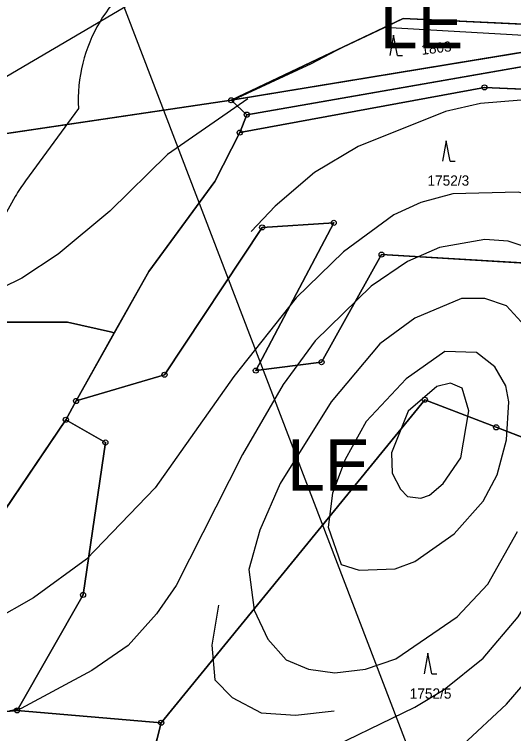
# Model space of a CAD drawing. Extents: x -706130 to -698555, y -971544 to -967260.
# Drawn here: x -703788.9 to -703691, y -970758.1 to -970617.2 of the extents above; entities that cross this region are included whole.
import ezdxf

# ---------------------------------------------------------------- set-up
doc = ezdxf.new("R2010")
doc.units = 0
for name, color, linetype in [('Archeologická naleziště S', 7, 'Continuous'), ('BPEJ hranice S', 7, 'Continuous'), ('BPEJ I-II trida ochrany S', 7, 'Continuous'), ('KN_Hranice_parcel', 7, 'Continuous'), ('KN_Parcelni cisla', 7, 'Continuous'), ('KN_Polygon parcely', 7, 'Continuous'), ('KN_POZEMKY_10_LESNI POZEMEK', 7, 'Continuous'), ('KN_POZEMKY_14_OSTATNI PLOCHA', 7, 'Continuous'), ('KN_POZEMKY_2_ORNA PUDA', 7, 'Continuous'), ('KN_VYUZITI_17_ostatni plocha_ostatni komunikace', 7, 'Continuous'), ('KN_Značky bodu BP', 7, 'Continuous'), ('KN_Značky kultur', 7, 'Continuous'), ('OP lesa 30 m', 7, 'Continuous'), ('Plochy lesní všeobecné S', 7, 'Continuous'), ('Plochy verejnych prostranstvi - komunikace ostatni S', 7, 'Continuous'), ('Plochy zemědělské všeobecné CELEK S', 7, 'Continuous'), ('Regulační bloky v krajině S', 7, 'Continuous'), ('Regulační bloky zastavěné S', 7, 'Continuous'), ('Regulační kódy v krajině S', 7, 'Continuous'), ('VÝŠKOPIS_vrstevnice doplňková', 7, 'Continuous'), ('VÝŠKOPIS_vrstevnice hlavní', 7, 'Continuous'), ('VÝŠKOPIS_vrstevnice zesílená', 7, 'Continuous')]:
    doc.layers.add(name, color=color, linetype=linetype)

msp = doc.modelspace()

# ---------------------------------------------------------------- linework, layer by layer
at = {"layer": 'Archeologická naleziště S'}
msp.add_lwpolyline([(-703408.7, -970993.88), (-703586.12, -970875.94), (-703659.44, -970897.19), (-703878.38, -970326.38), (-703591.19, -970210.38), (-703362.81, -970550.62), (-703335.44, -970886.44), (-703375.42, -970994.48)], dxfattribs=at)
at = {"layer": 'BPEJ hranice S'}
for points in [[(-703611.44, -970647.66), (-703616.01, -970640.13), (-703617.35, -970637.9), (-703628.15, -970631.35), (-703640.72, -970627.1), (-703661.7, -970626.61), (-703663.2, -970626.57), (-703664, -970624.6), (-703664.79, -970622.68), (-703674.27, -970622.13), (-703716.34, -970619.71), (-703724.46, -970623.57), (-703730.69, -970626.83), (-703745.91, -970633.92), (-703746.26, -970634.08), (-703743.32, -970636.82), (-703744.69, -970640.33), (-703749.57, -970649.91), (-703762.54, -970667.56), (-703769.3, -970679.59), (-703770.02, -970679.4), (-703778.45, -970677.49), (-703792, -970677.49)], [(-703796.23, -970722.36), (-703778.8, -970696.59), (-703776.78, -970692.92), (-703769.3, -970679.59), (-703770.02, -970679.4), (-703778.45, -970677.49), (-703792, -970677.49)]]:
    msp.add_lwpolyline(points, dxfattribs=at)
at = {"layer": 'BPEJ I-II trida ochrany S'}
for p, q in [((-703716.34, -970619.71), (-703712.67, -970617.96)), ((-703712.67, -970617.96), (-703663.27, -970620.32)), ((-703746.36, -970633.99), (-703724.46, -970623.57)), ((-703743.32, -970636.82), (-703746.36, -970633.99)), ((-703792, -970677.49), (-703778.45, -970677.49)), ((-703778.45, -970677.49), (-703770.02, -970679.4))]:
    msp.add_line(p, q, dxfattribs=at)
for points in [[(-703724.46, -970623.57), (-703724.46, -970623.57), (-703716.34, -970619.71), (-703716.34, -970619.71)], [(-703770.02, -970679.4), (-703769.3, -970679.59), (-703762.54, -970667.56), (-703749.57, -970649.91), (-703744.69, -970640.33), (-703743.32, -970636.82)]]:
    msp.add_lwpolyline(points, dxfattribs=at)
at = {"layer": 'KN_Hranice_parcel'}
for p, q in [((-703746.36, -970633.99), (-703663.27, -970620.32)), ((-703696.75, -970631.48), (-703744.69, -970640.33)), ((-703665.55, -970632.87), (-703696.75, -970631.48)), ((-703746.36, -970633.99), (-703845.42, -970648.65)), ((-703743.32, -970636.82), (-703746.36, -970633.99)), ((-703743.32, -970636.82), (-703744.69, -970640.33)), ((-703776.78, -970692.92), (-703759.45, -970687.77)), ((-703778.8, -970696.59), (-703776.78, -970692.92)), ((-703771.03, -970701.05), (-703778.8, -970696.59)), ((-703661.78, -970710.7), (-703694.43, -970698.08)), ((-703788.35, -970753.55), (-703835.64, -970758.02)), ((-703760.08, -970755.96), (-703788.35, -970753.55)), ((-703775.02, -970814.32), (-703760.08, -970755.96))]:
    msp.add_line(p, q, dxfattribs=at)
for points in [[(-703663.27, -970620.32), (-703712.67, -970617.96), (-703746.36, -970633.99)], [(-703660.69, -970624.97), (-703669.68, -970623.96), (-703743.32, -970636.82)], [(-703759.45, -970687.77), (-703740.3, -970658.91), (-703726.28, -970658.01), (-703741.54, -970686.96), (-703728.65, -970685.31), (-703716.89, -970664.24), (-703686.1, -970666.05), (-703665.55, -970632.87)], [(-703744.69, -970640.33), (-703749.57, -970649.91), (-703762.54, -970667.56), (-703776.78, -970692.92)], [(-703694.43, -970698.08), (-703708.42, -970692.67), (-703760.08, -970755.96)], [(-703835.64, -970758.02), (-703816.66, -970738.43), (-703796.23, -970722.36), (-703778.8, -970696.59)], [(-703788.35, -970753.55), (-703775.41, -970730.92), (-703771.03, -970701.05)]]:
    msp.add_lwpolyline(points, dxfattribs=at)
at = {"layer": 'KN_Polygon parcely'}
msp.add_lwpolyline([(-703939.69, -970610.55), (-703996, -970622.02), (-703989.78, -970655.74), (-703975.44, -970677.14), (-703944.34, -970667.67), (-703937.82, -970665.9), (-703864.08, -970651.3), (-703845.42, -970648.65), (-703746.36, -970633.99), (-703712.67, -970617.96), (-703663.27, -970620.32), (-703637.5, -970621.77), (-703629.23, -970623.8), (-703613.54, -970631.59), (-703573.25, -970635.06), (-703560.34, -970638.34), (-703550.3, -970642.25), (-703478.57, -970668.92), (-703476.26, -970659.93), (-703472.33, -970642.48), (-703487.91, -970603.31)], dxfattribs=at)
for points in [[(-703746.36, -970633.99), (-703663.27, -970620.32), (-703712.67, -970617.96)], [(-703615.1, -970635.19), (-703579.7, -970637.28), (-703562.88, -970640.25), (-703463.09, -970679), (-703454.84, -970679.15), (-703407.35, -970679.31), (-703407.75, -970675.61), (-703461.8, -970675.15), (-703478.57, -970668.92), (-703550.3, -970642.25), (-703560.34, -970638.34), (-703573.25, -970635.06), (-703613.54, -970631.59), (-703629.23, -970623.8), (-703637.5, -970621.77), (-703663.27, -970620.32), (-703746.36, -970633.99), (-703743.32, -970636.82), (-703669.68, -970623.96), (-703660.69, -970624.97), (-703639.83, -970624.72), (-703629.81, -970627.16)], [(-703669.68, -970623.96), (-703743.32, -970636.82), (-703744.69, -970640.33), (-703696.75, -970631.48), (-703665.55, -970632.87), (-703660.69, -970624.97)], [(-703760.08, -970755.96), (-703708.42, -970692.67), (-703694.43, -970698.08), (-703661.78, -970710.7), (-703651.67, -970713.29), (-703621.65, -970670.96), (-703615.1, -970635.19), (-703629.81, -970627.16), (-703639.83, -970624.72), (-703660.69, -970624.97), (-703665.55, -970632.87), (-703686.1, -970666.05), (-703716.89, -970664.24), (-703728.65, -970685.31), (-703741.54, -970686.96), (-703726.28, -970658.01), (-703740.3, -970658.91), (-703759.45, -970687.77), (-703776.78, -970692.92), (-703778.8, -970696.59), (-703771.03, -970701.05), (-703775.41, -970730.92), (-703788.35, -970753.55)], [(-703716.89, -970664.24), (-703686.1, -970666.05), (-703665.55, -970632.87), (-703696.75, -970631.48), (-703744.69, -970640.33), (-703749.57, -970649.91), (-703762.54, -970667.56), (-703776.78, -970692.92), (-703759.45, -970687.77), (-703740.3, -970658.91), (-703726.28, -970658.01), (-703741.54, -970686.96), (-703728.65, -970685.31)], [(-703778.8, -970696.59), (-703776.78, -970692.92), (-703762.54, -970667.56), (-703749.57, -970649.91), (-703744.69, -970640.33), (-703743.32, -970636.82), (-703746.36, -970633.99), (-703845.42, -970648.65), (-703864.08, -970651.3), (-703937.82, -970665.9), (-703944.34, -970667.67), (-703975.44, -970677.14), (-703961.3, -970781.02), (-703954.28, -970779.83), (-703945.45, -970778.27), (-703944.45, -970781.48), (-703927.53, -970774.91), (-703881.57, -970766.76), (-703835.64, -970758.02), (-703816.66, -970738.43), (-703796.23, -970722.36)], [(-703708.42, -970692.67), (-703760.08, -970755.96), (-703775.02, -970814.32), (-703732.08, -970781.35), (-703683.41, -970785.58), (-703676.23, -970759.35), (-703661.78, -970710.7), (-703694.43, -970698.08)], [(-703775.41, -970730.92), (-703771.03, -970701.05), (-703778.8, -970696.59), (-703796.23, -970722.36), (-703816.66, -970738.43), (-703835.64, -970758.02), (-703788.35, -970753.55)], [(-703775.02, -970814.32), (-703760.08, -970755.96), (-703788.35, -970753.55), (-703835.64, -970758.02), (-703881.57, -970766.76), (-703856.96, -970809.13), (-703851.88, -970814.56), (-703846.84, -970815.09), (-703839.77, -970813.83), (-703775.76, -970818.75), (-703772.64, -970816.86)]]:
    msp.add_lwpolyline(points, close=True, dxfattribs=at)
at = {"layer": 'KN_POZEMKY_10_LESNI POZEMEK'}
for p, q in [((-703746.36, -970633.99), (-703712.67, -970617.96)), ((-703712.67, -970617.96), (-703663.27, -970620.32)), ((-703663.27, -970620.32), (-703746.36, -970633.99)), ((-703743.32, -970636.82), (-703669.68, -970623.96)), ((-703696.75, -970631.48), (-703744.69, -970640.33)), ((-703744.69, -970640.33), (-703696.75, -970631.48)), ((-703665.55, -970632.87), (-703696.75, -970631.48)), ((-703696.75, -970631.48), (-703665.55, -970632.87)), ((-703744.69, -970640.33), (-703743.32, -970636.82)), ((-703749.57, -970649.91), (-703744.69, -970640.33)), ((-703762.54, -970667.56), (-703749.57, -970649.91)), ((-703726.28, -970658.01), (-703741.54, -970686.96)), ((-703741.54, -970686.96), (-703726.28, -970658.01)), ((-703740.3, -970658.91), (-703726.28, -970658.01)), ((-703726.28, -970658.01), (-703740.3, -970658.91)), ((-703759.45, -970687.77), (-703740.3, -970658.91)), ((-703740.3, -970658.91), (-703759.45, -970687.77)), ((-703728.65, -970685.31), (-703716.89, -970664.24)), ((-703716.89, -970664.24), (-703728.65, -970685.31)), ((-703716.89, -970664.24), (-703686.1, -970666.05)), ((-703686.1, -970666.05), (-703716.89, -970664.24)), ((-703776.78, -970692.92), (-703762.54, -970667.56)), ((-703741.54, -970686.96), (-703728.65, -970685.31)), ((-703728.65, -970685.31), (-703741.54, -970686.96)), ((-703776.78, -970692.92), (-703759.45, -970687.77)), ((-703759.45, -970687.77), (-703776.78, -970692.92)), ((-703778.8, -970696.59), (-703776.78, -970692.92)), ((-703708.42, -970692.67), (-703760.08, -970755.96)), ((-703760.08, -970755.96), (-703708.42, -970692.67)), ((-703694.43, -970698.08), (-703708.42, -970692.67)), ((-703708.42, -970692.67), (-703694.43, -970698.08)), ((-703796.23, -970722.36), (-703778.8, -970696.59)), ((-703771.03, -970701.05), (-703778.8, -970696.59)), ((-703778.8, -970696.59), (-703771.03, -970701.05)), ((-703661.78, -970710.7), (-703694.43, -970698.08)), ((-703694.43, -970698.08), (-703661.78, -970710.7)), ((-703775.41, -970730.92), (-703771.03, -970701.05)), ((-703771.03, -970701.05), (-703775.41, -970730.92)), ((-703788.35, -970753.55), (-703775.41, -970730.92)), ((-703775.41, -970730.92), (-703788.35, -970753.55)), ((-703835.64, -970758.02), (-703788.35, -970753.55)), ((-703788.35, -970753.55), (-703835.64, -970758.02)), ((-703788.35, -970753.55), (-703760.08, -970755.96)), ((-703760.08, -970755.96), (-703788.35, -970753.55)), ((-703760.08, -970755.96), (-703775.02, -970814.32)), ((-703775.02, -970814.32), (-703760.08, -970755.96))]:
    msp.add_line(p, q, dxfattribs=at)
at = {"layer": 'KN_POZEMKY_14_OSTATNI PLOCHA'}
for p, q in [((-703746.36, -970633.99), (-703663.27, -970620.32)), ((-703669.68, -970623.96), (-703743.32, -970636.82)), ((-703743.32, -970636.82), (-703746.36, -970633.99))]:
    msp.add_line(p, q, dxfattribs=at)
at = {"layer": 'KN_POZEMKY_2_ORNA PUDA'}
for p, q in [((-703712.67, -970617.96), (-703746.36, -970633.99)), ((-703663.27, -970620.32), (-703712.67, -970617.96)), ((-703845.42, -970648.65), (-703746.36, -970633.99)), ((-703746.36, -970633.99), (-703845.42, -970648.65)), ((-703746.36, -970633.99), (-703743.32, -970636.82)), ((-703743.32, -970636.82), (-703744.69, -970640.33)), ((-703744.69, -970640.33), (-703749.57, -970649.91)), ((-703749.57, -970649.91), (-703762.54, -970667.56)), ((-703762.54, -970667.56), (-703776.78, -970692.92)), ((-703776.78, -970692.92), (-703778.8, -970696.59)), ((-703778.8, -970696.59), (-703796.23, -970722.36))]:
    msp.add_line(p, q, dxfattribs=at)
at = {"layer": 'KN_VYUZITI_17_ostatni plocha_ostatni komunikace'}
for p, q in [((-703746.36, -970633.99), (-703663.27, -970620.32)), ((-703669.68, -970623.96), (-703743.32, -970636.82)), ((-703743.32, -970636.82), (-703746.36, -970633.99))]:
    msp.add_line(p, q, dxfattribs=at)
at = {"layer": 'KN_Značky bodu BP'}
for centre, radius in [((-703696.75, -970631.48), 0.5), ((-703696.75, -970631.48), 0.0303), ((-703746.36, -970633.99), 0.5), ((-703746.36, -970633.99), 0.0303), ((-703743.32, -970636.82), 0.5), ((-703743.32, -970636.82), 0.0303), ((-703744.69, -970640.33), 0.5), ((-703744.69, -970640.33), 0.0303), ((-703726.28, -970658.01), 0.5), ((-703726.28, -970658.01), 0.0303), ((-703740.3, -970658.91), 0.5), ((-703740.3, -970658.91), 0.0303), ((-703716.89, -970664.24), 0.5), ((-703716.89, -970664.24), 0.0303), ((-703728.65, -970685.31), 0.5), ((-703741.54, -970686.96), 0.5), ((-703728.65, -970685.31), 0.0303), ((-703759.45, -970687.77), 0.5), ((-703759.45, -970687.77), 0.0303), ((-703741.54, -970686.96), 0.0303), ((-703708.42, -970692.67), 0.5), ((-703776.78, -970692.92), 0.5), ((-703776.78, -970692.92), 0.0303), ((-703708.42, -970692.67), 0.0303), ((-703778.8, -970696.59), 0.5), ((-703778.8, -970696.59), 0.0303), ((-703694.43, -970698.08), 0.5), ((-703694.43, -970698.08), 0.0303), ((-703771.03, -970701.05), 0.5), ((-703771.03, -970701.05), 0.0303), ((-703775.41, -970730.92), 0.5), ((-703775.41, -970730.92), 0.0303), ((-703788.35, -970753.55), 0.5), ((-703788.35, -970753.55), 0.0303), ((-703760.08, -970755.96), 0.5), ((-703760.08, -970755.96), 0.0303)]:
    msp.add_circle(centre, radius, dxfattribs=at)
at = {"layer": 'KN_Značky kultur'}
for p, q in [((-703714.54, -970621.22), (-703715.29, -970625.22)), ((-703713.79, -970625.22), (-703714.54, -970621.22)), ((-703713.79, -970625.22), (-703712.79, -970625.22)), ((-703704.22, -970641.96), (-703704.97, -970645.96)), ((-703703.47, -970645.96), (-703704.22, -970641.96)), ((-703703.47, -970645.96), (-703702.47, -970645.96)), ((-703707.81, -970742.36), (-703708.56, -970746.36)), ((-703707.06, -970746.36), (-703707.81, -970742.36)), ((-703707.06, -970746.36), (-703706.06, -970746.36))]:
    msp.add_line(p, q, dxfattribs=at)
at = {"layer": 'OP lesa 30 m'}
for p, q in [((-703776.31, -970635.64), (-703786.71, -970649.8)), ((-703788.7, -970652.87), (-703802.94, -970678.23))]:
    msp.add_line(p, q, dxfattribs=at)
for centre, start, end in [((-703746.36, -970633.99), 115.4455, 183.1573), ((-703762.54, -970667.56), 143.6899, 150.6852)]:
    msp.add_arc(centre, 30, start, end, dxfattribs=at)
at = {"layer": 'Plochy lesní všeobecné S'}
for p, q in [((-703712.67, -970617.96), (-703746.36, -970633.99)), ((-703663.27, -970620.32), (-703712.67, -970617.96)), ((-703746.36, -970633.99), (-703663.27, -970620.32)), ((-703669.68, -970623.96), (-703743.32, -970636.82)), ((-703743.32, -970636.82), (-703744.69, -970640.33)), ((-703744.69, -970640.33), (-703749.57, -970649.91)), ((-703749.57, -970649.91), (-703762.54, -970667.56)), ((-703762.54, -970667.56), (-703776.78, -970692.92)), ((-703776.78, -970692.92), (-703778.8, -970696.59)), ((-703778.8, -970696.59), (-703796.23, -970722.36))]:
    msp.add_line(p, q, dxfattribs=at)
at = {"layer": 'Plochy verejnych prostranstvi - komunikace ostatni S'}
for p, q in [((-703743.32, -970636.82), (-703669.68, -970623.96)), ((-703746.36, -970633.99), (-703743.32, -970636.82))]:
    msp.add_line(p, q, dxfattribs=at)
msp.add_lwpolyline([(-703629.23, -970623.8), (-703637.5, -970621.77), (-703663.27, -970620.32), (-703746.36, -970633.99)], dxfattribs=at)
at = {"layer": 'Plochy zemědělské všeobecné CELEK S'}
for p, q in [((-703746.36, -970633.99), (-703712.67, -970617.96)), ((-703712.67, -970617.96), (-703663.27, -970620.32)), ((-703743.32, -970636.82), (-703746.36, -970633.99)), ((-703744.69, -970640.33), (-703743.32, -970636.82)), ((-703749.57, -970649.91), (-703744.69, -970640.33)), ((-703762.54, -970667.56), (-703749.57, -970649.91)), ((-703776.78, -970692.92), (-703762.54, -970667.56)), ((-703778.8, -970696.59), (-703776.78, -970692.92)), ((-703796.23, -970722.36), (-703778.8, -970696.59))]:
    msp.add_line(p, q, dxfattribs=at)
at = {"layer": 'Regulační bloky v krajině S'}
for p, q in [((-703712.67, -970617.96), (-703746.36, -970633.99)), ((-703746.36, -970633.99), (-703712.67, -970617.96)), ((-703663.27, -970620.32), (-703712.67, -970617.96)), ((-703712.67, -970617.96), (-703663.27, -970620.32)), ((-703746.36, -970633.99), (-703663.27, -970620.32)), ((-703669.68, -970623.96), (-703743.32, -970636.82)), ((-703743.32, -970636.82), (-703746.36, -970633.99)), ((-703743.32, -970636.82), (-703744.69, -970640.33)), ((-703744.69, -970640.33), (-703743.32, -970636.82)), ((-703744.69, -970640.33), (-703749.57, -970649.91)), ((-703749.57, -970649.91), (-703744.69, -970640.33)), ((-703749.57, -970649.91), (-703762.54, -970667.56)), ((-703762.54, -970667.56), (-703749.57, -970649.91)), ((-703762.54, -970667.56), (-703776.78, -970692.92)), ((-703776.78, -970692.92), (-703762.54, -970667.56)), ((-703776.78, -970692.92), (-703778.8, -970696.59)), ((-703778.8, -970696.59), (-703776.78, -970692.92)), ((-703778.8, -970696.59), (-703796.23, -970722.36)), ((-703796.23, -970722.36), (-703778.8, -970696.59))]:
    msp.add_line(p, q, dxfattribs=at)
at = {"layer": 'Regulační bloky zastavěné S'}
for p, q in [((-703743.32, -970636.82), (-703669.68, -970623.96)), ((-703746.36, -970633.99), (-703743.32, -970636.82))]:
    msp.add_line(p, q, dxfattribs=at)
msp.add_lwpolyline([(-703629.23, -970623.8), (-703637.5, -970621.77), (-703663.27, -970620.32), (-703746.36, -970633.99)], dxfattribs=at)
at = {"layer": 'VÝŠKOPIS_vrstevnice doplňková'}
for points in [[(-703704.8, -970709.09), (-703701.38, -970704.08), (-703699.81, -970694.82), (-703701.09, -970690.4), (-703703.38, -970689.4), (-703706.04, -970690.08), (-703711.66, -970694.89), (-703714.93, -970703.1), (-703714.79, -970707.09), (-703713.22, -970710.23), (-703711.79, -970711.66), (-703709.23, -970711.94), (-703707.51, -970711.37), (-703704.8, -970709.09)], [(-703748.89, -970732.92), (-703750.17, -970740.76), (-703749.59, -970747.58), (-703746.18, -970751.04), (-703740.47, -970754.03), (-703733.77, -970754.46), (-703726.2, -970753.6)]]:
    msp.add_lwpolyline(points, dxfattribs=at)
at = {"layer": 'VÝŠKOPIS_vrstevnice hlavní'}
for points in [[(-703762.3, -970612.79), (-703794.54, -970631.76), (-703804.82, -970637.04), (-703810.52, -970638.75), (-703818.51, -970639.18), (-703828.5, -970637.61), (-703865.02, -970626.77), (-703873.01, -970626.2), (-703881.57, -970627.34), (-703890.13, -970630.05)], [(-703743.12, -970633.7), (-703758.88, -970644.6), (-703770.15, -970655.73), (-703780.28, -970664.15), (-703787.41, -970668.86), (-703795.33, -970672.68), (-703853.32, -970692.54), (-703864.45, -970698.11), (-703872.73, -970705.1), (-703884, -970718.79)], [(-703649.02, -970664.01), (-703653.73, -970654.02), (-703658.15, -970648.03), (-703665.57, -970640.61), (-703671.85, -970636.9), (-703680.41, -970634.19), (-703685.54, -970633.62), (-703697.53, -970634.62), (-703704.37, -970636.19), (-703721.5, -970643.03), (-703730.06, -970648.17), (-703737.76, -970654.73), (-703742.47, -970659.73)], [(-703730.34, -970762.59), (-703710.37, -970752.89), (-703704.66, -970749.47), (-703696.96, -970743.33), (-703690.11, -970735.2), (-703686.4, -970729.21), (-703681.83, -970719.93), (-703677.84, -970707.95), (-703674.98, -970687.98), (-703675.41, -970679.99), (-703676.27, -970675.99), (-703678.98, -970669.86), (-703681.98, -970666.58), (-703686.97, -970663.29), (-703692.11, -970661.58), (-703696.67, -970661.3), (-703705.52, -970662.87), (-703711.79, -970665.58), (-703718.93, -970670.43), (-703729.91, -970681.13), (-703736.19, -970689.69), (-703744.18, -970703.38), (-703757.16, -970729.06), (-703761.01, -970734.63)], [(-703689.54, -970677.42), (-703692.39, -970674.28), (-703696.67, -970672.85), (-703701.24, -970672.85), (-703710.37, -970676.7), (-703717.22, -970681.7), (-703726.77, -970693.11), (-703736.76, -970709.09), (-703740.76, -970718.22), (-703742.9, -970725.93), (-703741.9, -970733.92), (-703739.19, -970739.62), (-703735.62, -970743.62), (-703731.2, -970745.47), (-703726.06, -970746.18)], [(-703714.22, -970725.78), (-703710.37, -970724.36), (-703702.66, -970718.94), (-703696.96, -970712.52), (-703694.24, -970707.38), (-703692.39, -970700.53), (-703691.96, -970693.11), (-703692.53, -970689.97), (-703694.67, -970686.26), (-703698.28, -970683.41), (-703704.5, -970683.21), (-703712.08, -970688.55), (-703719.93, -970696.96), (-703724.06, -970704.38), (-703726.49, -970710.95), (-703727.34, -970717.65), (-703724.8, -970724.96), (-703721.29, -970726.06), (-703714.22, -970725.78)], [(-703726.06, -970746.18), (-703720.07, -970745.47), (-703714.08, -970743.47), (-703702.09, -970735.2), (-703696.1, -970728.78), (-703690.25, -970718.51)], [(-703761.01, -970734.63), (-703766.57, -970740.84), (-703773.71, -970745.76), (-703787.55, -970753.18), (-703789.69, -970753.6)]]:
    msp.add_lwpolyline(points, dxfattribs=at)
at = {"layer": 'VÝŠKOPIS_vrstevnice zesílená'}
for points in [[(-703700.95, -970760.31), (-703692.39, -970752.32), (-703681.4, -970739.62), (-703673.84, -970727.35), (-703668.42, -970714.8), (-703666.57, -970708.52), (-703664.43, -970696.25), (-703664.71, -970684.27), (-703666.85, -970672.28), (-703669.28, -970666.29), (-703677.84, -970655.87), (-703683.55, -970653.59), (-703690.11, -970652.02), (-703702.95, -970652.31), (-703709.23, -970654.02), (-703714.5, -970656.45)], [(-703714.5, -970656.45), (-703724.35, -970663.72), (-703733.62, -970672.71), (-703745.89, -970688.12), (-703761.3, -970709.95), (-703774.71, -970723.93), (-703785.13, -970731.49), (-703817.37, -970749.75), (-703827.21, -970757.17), (-703831.35, -970761.74), (-703834.92, -970766.87), (-703844.05, -970783.14), (-703850.9, -970793.69), (-703862.02, -970807.96), (-703870.44, -970816.81), (-703875.29, -970820.66), (-703919.52, -970844.2)]]:
    msp.add_lwpolyline(points, dxfattribs=at)

# ---------------------------------------------------------------- texts
at = {"layer": 'KN_Parcelni cisla'}
msp.add_text('1803', height=2, rotation=7, dxfattribs=at).set_placement((-703709, -970625.11))
for s, p in [('1752/3', (-703707.9, -970650.73)), ('1752/5', (-703711.38, -970751.24))]:
    msp.add_text(s, height=2, dxfattribs=at).set_placement(p)
at = {"layer": 'Regulační kódy v krajině S'}
for p in [(-703717.26, -970623.81), (-703735.45, -970710.46)]:
    msp.add_text('LE', height=10, dxfattribs=at).set_placement(p)

doc.saveas('drawing.dxf')
